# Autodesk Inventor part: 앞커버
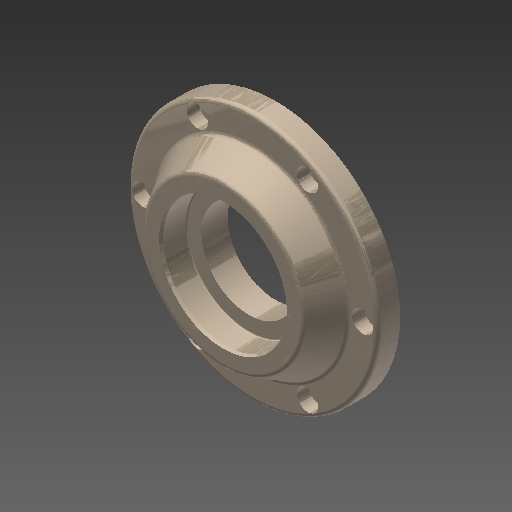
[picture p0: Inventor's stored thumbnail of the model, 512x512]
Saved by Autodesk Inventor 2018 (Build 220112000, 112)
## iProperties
Created: 2013-01
Part Number: 앞커버
Document SubType Name: Modeling
Designer: 한국산업디자인학원[gmhk.co.kr]
Density: 2.71 g/cm^3
Material: 알루미늄 6061
Mass: 415.969 g
Surface Area: 272.105 cm^2
Volume: 153.494 cm^3
Appearance: 알루미늄 - 평지(2)
Author: 한국산업디자인학원[gmhk.co.kr]
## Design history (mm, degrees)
sketch "스케치2"
  geometry: L1 (-55, 0)-(55, 0) reference; L2 (35.98, -6)-(-35.98, -6) reference; L3 (-42.5, -25)-(-42.5, 0) reference; L4 (-37, -6)-(-37, 0); L5 (-55, 0)-(-55, 10); L6 (-55, 10)-(-42.5, 10); L7 (-37, -6)-(-42.5, -6); L8 (-42.5, 10)-(-34.994, 23); L9 (-34.994, 23)-(0, 23); L10 (-55, 0)-(-42.5, 0); L11 (-42.5, -6)-(-42.5, 0); L12 (0, 0)-(0, 23); L13 (0, 0)-(-37, 0)
  constraints: 22 end point, 4 perpendicular, 3 collinear, 2 parallel, 2 point on line, 1 vertical, 2 other
  dimensions: "d2" = 10 distance of L1.start L5.end; "d4" = 120 deg angle of L8 L6; "d5" = 13 distance between parallel lines of L6 L9; "d6" = 74 diameter of L4 L12; "d7" = 85 diameter of L6.end L12
revolve "회전1" sketch "스케치2" stored, may be unused: angle "d8" = 90 deg
fillet "모깎기1" dims "d9" = 2
sketch "스케치3"
  geometry: C1 r 2.067 at (48.5, 0) reference; 1 further point
hole "구멍1" sketch "스케치3" at (48.5, 0) diameter "d10" = 5.5; stored, may be unused: countersink angle "d14" = 90 deg, drill point angle "d16" = 118 deg; dims "d11" = 6, "d12" = 9.5, "d13" = 5.4, "d15" = 8
fillet "모깎기2" dims "d20" = 3
chamfer "모따기1" distance "d21" = 1; stored, may be unused: second distance "d22" = 2, angle "d23" = 45 deg
sketch "스케치4"
  geometry: L1 (-33.84, 23)-(33.84, 23) reference; L2 (34, 0)-(-34, 0) reference; L3 (0, 0)-(0, 23); L4 (27.5, 21.9)-(27.5, 12.1); L5 (27, 11.6)-(21, 11.6); L6 (21, 11.6)-(21, 0); L7 (27.5, 21.9)-(28.135, 23); A1 r 0.5 centre (27, 12.1) between (27, 11.6) and (27.5, 12.1)
  constraints: 10 end point, 2 perpendicular, 2 point on circle, 2 point on line, 2 tangent, 1 centre point, 1 midpoint, 1 parallel
  dimensions: "d24" = 11.4 distance between parallel lines of L5 L1; "d25" = 1.1 distance from line of L4.start L1; "d26" = 30 deg angle of L7 L4; "d27" = 0.5 radius of A1; "d28" = 55 diameter of L4 L3; "d29" = 42 diameter of L6 L3
revolve "회전2" sketch "스케치4" stored, may be unused: angle "d30" = 90 deg
node "솔리드1"
pattern_circular "원형 패턴1" dims angle "d18" = 360 deg
node "참조1"
node "참조2"
node "참조3"
